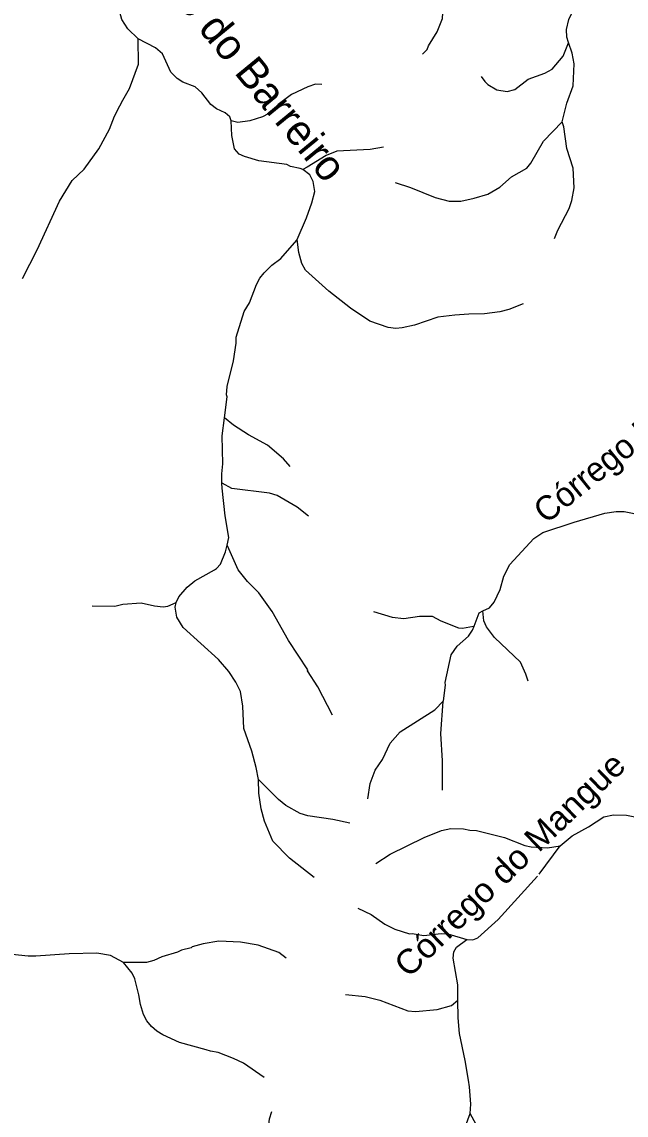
# Model space of a CAD drawing. Extents: x 393 to 446.6, y 8175.5 to 8231.
# Drawn here: x 422.17 to 426.13, y 8197.16 to 8204.34 of the extents above; entities that cross this region are included whole.
import ezdxf
from ezdxf.enums import TextEntityAlignment as Align

# ---------------------------------------------------------------- set-up
doc = ezdxf.new("R2010")
doc.units = 0
doc.header["$LTSCALE"] = 0.064
doc.linetypes.add('LONG_DASHED', pattern=[7.5, 6, -1.5])
doc.layers.add('61', color=7, linetype='Continuous')
doc.layers.add('7', color=7, linetype='Continuous', lineweight=25)
doc.layers.add('9', color=7, linetype='LONG_DASHED', lineweight=25)

msp = doc.modelspace()

# ---------------------------------------------------------------- linework, layer by layer
at = {"layer": '7'}
for points in [[(424.7977, 8204.1324), (424.8272, 8204.1627), (424.8352, 8204.1869), (424.8933, 8204.279), (424.9289, 8204.3662), (424.9305, 8204.4049), (424.9289, 8204.4517), (424.9208, 8204.4873), (424.874, 8204.6019), (424.8804, 8204.757), (424.8449, 8204.9055), (424.8449, 8204.954), (424.8611, 8205.0541), (424.8546, 8205.2382), (424.7771, 8205.4386)], [(425.7561, 8204.2094), (425.7441, 8204.2442), (425.7427, 8204.2951), (425.7572, 8204.3597), (425.7938, 8204.437)], [(425.1822, 8203.9863), (425.205, 8203.9528), (425.226, 8203.9334), (425.2842, 8203.8979), (425.352, 8203.8866), (425.4037, 8203.9011), (425.4908, 8203.9673), (425.6007, 8204.0077), (425.6475, 8204.0335), (425.7201, 8204.1191), (425.7546, 8204.2058), (425.7561, 8204.2094)], [(425.7149, 8203.6883), (425.7443, 8203.8107), (425.7863, 8203.9237), (425.7928, 8204.0691), (425.7799, 8204.1401), (425.7561, 8204.2094)], [(424.6181, 8203.2893), (424.719, 8203.2568), (424.8805, 8203.1906), (424.9709, 8203.1664), (425.0484, 8203.168), (425.1356, 8203.1857), (425.226, 8203.2132), (425.3035, 8203.2584), (425.381, 8203.3278), (425.4812, 8203.3827), (425.5086, 8203.4166), (425.5909, 8203.562), (425.7149, 8203.6883)], [(425.6641, 8202.9212), (425.6846, 8202.9775), (425.7589, 8203.1196), (425.7783, 8203.1712), (425.7928, 8203.2552), (425.7863, 8203.3844), (425.7443, 8203.5136), (425.725, 8203.6557), (425.7149, 8203.6883)], [(423.9025, 8198.1952), (423.8534, 8198.2332), (423.7178, 8198.2816), (423.6015, 8198.2994), (423.4594, 8198.3058), (423.3561, 8198.2897), (423.285, 8198.2703), (423.2786, 8198.2638), (423.214, 8198.2477), (423.1882, 8198.2348), (423.0848, 8198.2041), (423.0331, 8198.1799), (422.9847, 8198.1669), (422.8338, 8198.1671)], [(422.8338, 8198.1671), (422.7489, 8198.2122), (422.6585, 8198.2283), (422.4776, 8198.2235), (422.258, 8198.2073), (422.2064, 8198.2073), (422.103, 8198.2202)], [(423.7564, 8197.4116), (423.6209, 8197.5065), (423.5563, 8197.5356), (423.4546, 8197.576), (423.4055, 8197.5841), (423.3769, 8197.5922), (423.201, 8197.6422), (423.0913, 8197.6906), (423.0525, 8197.7148), (423.017, 8197.7455), (422.9863, 8197.7826), (422.9637, 8197.8263), (422.9443, 8197.8909), (422.9346, 8197.9554), (422.9087, 8198.0588), (422.891, 8198.0975), (422.8338, 8198.1671)]]:
    msp.add_lwpolyline(points, dxfattribs=at)
at = {"layer": '9'}
for points in [[(422.9301, 8204.2332), (422.8613, 8204.2997), (422.8216, 8204.3592), (422.8052, 8204.4233), (422.757, 8204.5325), (422.6811, 8204.6568), (422.6568, 8204.786), (422.6375, 8204.983), (422.6165, 8205.0428), (422.5761, 8205.0993), (422.5676, 8205.151)], [(422.1695, 8202.6585), (422.267, 8202.8469), (422.4131, 8203.1664), (422.497, 8203.302), (422.5745, 8203.3779), (422.6714, 8203.5103), (422.7408, 8203.6395), (422.7748, 8203.7251), (422.8092, 8203.7931), (422.828, 8203.8301), (422.8732, 8203.9076), (422.9314, 8204.0674), (422.9301, 8204.2332)], [(423.5403, 8203.695), (423.5309, 8203.7206), (423.5006, 8203.7463), (423.4449, 8203.7735), (423.4061, 8203.801), (423.348, 8203.8785), (423.3044, 8203.9173), (423.222, 8203.9479), (423.1849, 8203.9721), (423.1445, 8204.0142), (423.0896, 8204.1336), (423.0444, 8204.174), (422.9301, 8204.2332)], [(424.1365, 8203.9338), (424.0933, 8203.9349), (424.044, 8203.9189), (423.9374, 8203.8672), (423.8486, 8203.801), (423.784, 8203.7412), (423.7472, 8203.7208), (423.6632, 8203.694), (423.5838, 8203.6846), (423.5403, 8203.695)], [(424.0106, 8203.3745), (423.9942, 8203.3815), (423.931, 8203.3956), (423.9051, 8203.407), (423.721, 8203.4328), (423.6274, 8203.4602), (423.5919, 8203.4764), (423.5628, 8203.5103), (423.545, 8203.5975), (423.5403, 8203.695)], [(424.5402, 8203.5221), (424.4525, 8203.5071), (424.2345, 8203.4958), (424.1651, 8203.4667), (424.0404, 8203.3901), (424.0106, 8203.3745)], [(423.9733, 8202.915), (424.0359, 8203.0582), (424.0698, 8203.1567), (424.0892, 8203.2294), (424.0779, 8203.2972), (424.0572, 8203.3407), (424.0106, 8203.3745)], [(423.4966, 8201.7445), (423.5136, 8201.8825), (423.5095, 8201.8955), (423.5143, 8201.9488), (423.5547, 8202.1184), (423.574, 8202.2346), (423.574, 8202.2734), (423.6257, 8202.4413), (423.6612, 8202.4995), (423.7065, 8202.6189), (423.7291, 8202.661), (423.7565, 8202.6964), (423.8082, 8202.7465), (423.8664, 8202.7901), (423.971, 8202.9098), (423.9733, 8202.915)], [(425.4569, 8202.4928), (425.3641, 8202.4549), (425.3035, 8202.4397), (425.2034, 8202.4268), (425.1001, 8202.4252), (425.0096, 8202.4187), (424.8982, 8202.4058), (424.7432, 8202.3525), (424.6641, 8202.3347), (424.6221, 8202.3315), (424.572, 8202.3364), (424.4509, 8202.3783), (424.325, 8202.4639), (424.1812, 8202.5753), (424.1596, 8202.595), (424.0294, 8202.7142), (424.0036, 8202.7578), (423.9842, 8202.8289), (423.9733, 8202.9148), (423.9733, 8202.915)], [(423.4798, 8201.3146), (423.4788, 8201.3755), (423.4853, 8201.4418), (423.482, 8201.6259), (423.4966, 8201.7445)], [(423.9269, 8201.4236), (423.8837, 8201.4737), (423.7792, 8201.5645), (423.6532, 8201.6323), (423.5563, 8201.6953), (423.4966, 8201.7445)], [(424.0471, 8201.0976), (423.9745, 8201.1576), (423.843, 8201.2342), (423.7917, 8201.2494), (423.5442, 8201.2797), (423.481, 8201.314), (423.4798, 8201.3146)], [(423.5134, 8200.9068), (423.5258, 8200.9585), (423.5014, 8201.1011), (423.4804, 8201.2819), (423.4798, 8201.3146)], [(425.1927, 8200.4758), (425.2357, 8200.4971), (425.2663, 8200.5326), (425.3067, 8200.6166), (425.331, 8200.7038), (425.3697, 8200.7797), (425.528, 8200.9525), (425.5877, 8200.9912), (425.7928, 8201.0591), (425.993, 8201.1172), (426.0689, 8201.1285), (426.1206, 8201.1285), (426.2401, 8201.1043), (426.3112, 8201.1059), (426.3386, 8201.1123), (426.4181, 8201.1504), (426.4345, 8201.1655)], [(423.18, 8200.5311), (423.1964, 8200.5673), (423.2511, 8200.6327), (423.3028, 8200.6731), (423.4308, 8200.7467), (423.4433, 8200.7539), (423.4707, 8200.7829), (423.503, 8200.8637), (423.5134, 8200.9068)], [(424.2061, 8199.7919), (424.1102, 8199.9772), (424.0424, 8200.0821), (424.044, 8200.0886), (423.9162, 8200.2816), (423.8106, 8200.4724), (423.7226, 8200.594), (423.6493, 8200.6674), (423.6484, 8200.6683), (423.587, 8200.7458), (423.5153, 8200.9025), (423.5134, 8200.9068)], [(422.6283, 8200.5098), (422.7765, 8200.5074), (422.8297, 8200.5197), (422.9492, 8200.5294), (423.038, 8200.5084), (423.0945, 8200.5036), (423.1236, 8200.5068), (423.18, 8200.5311)], [(423.7188, 8199.3677), (423.7048, 8199.4482), (423.6758, 8199.5557), (423.6225, 8199.7027), (423.6177, 8199.8512), (423.6015, 8199.9465), (423.5708, 8200.0078), (423.524, 8200.0773), (423.4562, 8200.1564), (423.2253, 8200.3663), (423.1833, 8200.4358), (423.1736, 8200.5004), (423.18, 8200.5311)], [(424.4757, 8200.4719), (424.5979, 8200.4341), (424.6738, 8200.426), (424.7771, 8200.4406), (424.8611, 8200.4406), (424.9166, 8200.4106), (425.0322, 8200.3651), (425.0585, 8200.3622), (425.1318, 8200.376), (425.1349, 8200.3766)], [(425.1349, 8200.3766), (425.168, 8200.4635), (425.1927, 8200.4758)], [(425.4899, 8200.0148), (425.4759, 8200.0614), (425.4397, 8200.1396), (425.2696, 8200.3017), (425.2179, 8200.3712), (425.2002, 8200.4099), (425.1927, 8200.4758)], [(424.9337, 8199.8846), (424.9482, 8199.9885), (424.945, 8200.0062), (424.9854, 8200.1871), (425.0241, 8200.2436), (425.0984, 8200.3098), (425.1242, 8200.3486), (425.1349, 8200.3766)], [(424.4375, 8199.2422), (424.4526, 8199.3413), (424.4865, 8199.43), (424.5338, 8199.4994), (424.5851, 8199.6067), (424.6495, 8199.6816), (424.8788, 8199.8253), (424.9336, 8199.8845), (424.9337, 8199.8846)], [(424.9277, 8199.2975), (424.9277, 8199.4911), (424.9176, 8199.6704), (424.9331, 8199.8804), (424.9337, 8199.8846)], [(424.3193, 8199.0823), (424.2073, 8199.1068), (424.044, 8199.1294), (423.9939, 8199.1455), (423.8987, 8199.1988), (423.8518, 8199.2376), (423.7188, 8199.3677)], [(424.0862, 8198.7241), (423.9227, 8198.8512), (423.813, 8198.9631), (423.7598, 8199.0955), (423.7372, 8199.1762), (423.721, 8199.2796), (423.7188, 8199.3677)], [(425.7007, 8198.9319), (425.78, 8198.9995), (425.8865, 8199.0583), (425.9866, 8199.1229), (426.0512, 8199.1375), (426.1368, 8199.1342), (426.203, 8199.1213), (426.2853, 8199.0777), (426.3402, 8199.0373), (426.4064, 8198.9663), (426.5194, 8198.779), (426.576, 8198.6676), (426.5953, 8198.6433), (426.6357, 8198.6143), (426.7044, 8198.5881), (426.7443, 8198.5808)], [(424.4914, 8198.817), (424.5848, 8198.8788), (424.8078, 8198.9873), (424.9224, 8199.0341), (424.9838, 8199.047), (425.0661, 8199.0454), (425.1065, 8199.0357), (425.1517, 8199.0341), (425.3358, 8198.9873), (425.4682, 8198.9356), (425.5102, 8198.9259), (425.6168, 8198.9194), (425.7007, 8198.9319)], [(425.087, 8198.3173), (425.1267, 8198.3162), (425.1594, 8198.329), (425.2938, 8198.4495), (425.5619, 8198.7467), (425.7007, 8198.9319)], [(424.3722, 8198.5233), (424.4606, 8198.4818), (424.5494, 8198.4189), (424.614, 8198.3866), (424.7109, 8198.3559), (424.7287, 8198.3575), (424.8045, 8198.343), (424.9192, 8198.3575), (424.9628, 8198.3559), (425.087, 8198.3173)], [(425.0296, 8197.92), (425.0288, 8198.0208), (424.9983, 8198.1944), (425.0015, 8198.2364), (425.0193, 8198.2671), (425.087, 8198.3173)], [(424.2908, 8197.9575), (424.2922, 8197.9574), (424.4202, 8197.9441), (424.5155, 8197.9183), (424.7012, 8197.8488), (424.7513, 8197.844), (424.8933, 8197.8588), (424.9867, 8197.8845), (425.0288, 8197.9193), (425.0296, 8197.92)], [(425.1108, 8197.174), (425.1143, 8197.237), (425.105, 8197.3501), (425.098, 8197.3942), (425.0776, 8197.5221), (425.0387, 8197.7003), (425.0306, 8197.8037), (425.0296, 8197.92)], [(423.8046, 8197.185), (423.7906, 8197.1372), (423.7548, 8196.8806), (423.7384, 8196.8317), (423.6919, 8196.7379), (423.6015, 8196.6168), (423.4804, 8196.4876), (423.3514, 8196.3797), (423.2606, 8196.3256)], [(424.3011, 8196.6884), (424.3416, 8196.6952), (424.6269, 8196.7427), (424.7933, 8196.7863), (424.8837, 8196.8444), (424.9596, 8196.9203), (425.0048, 8196.972), (425.0694, 8197.0673), (425.1108, 8197.174)], [(425.6943, 8196.6555), (425.6701, 8196.6587), (425.4505, 8196.8008), (425.2922, 8196.9155), (425.2163, 8196.9963), (425.1743, 8197.0544), (425.1108, 8197.174)]]:
    msp.add_lwpolyline(points, dxfattribs=at)

# ---------------------------------------------------------------- texts
at = {"layer": '61'}
for s, height, rotation, p in [('Córrego do Barreiro', 0.2, 309.388, (423.4091, 8204.1889)), ('Córrego Barreirinho', 0.16, 38.941, (426.3389, 8201.6331))]:
    msp.add_text(s, height=height, rotation=rotation, dxfattribs=at).set_placement(p, align=Align.CENTER)
at = {"layer": '61', "width": 1.05}
msp.add_text('Córrego do Mangue', height=0.16, rotation=43.984, dxfattribs=at).set_placement((425.4249, 8198.7535), align=Align.CENTER)

doc.saveas('drawing.dxf')
